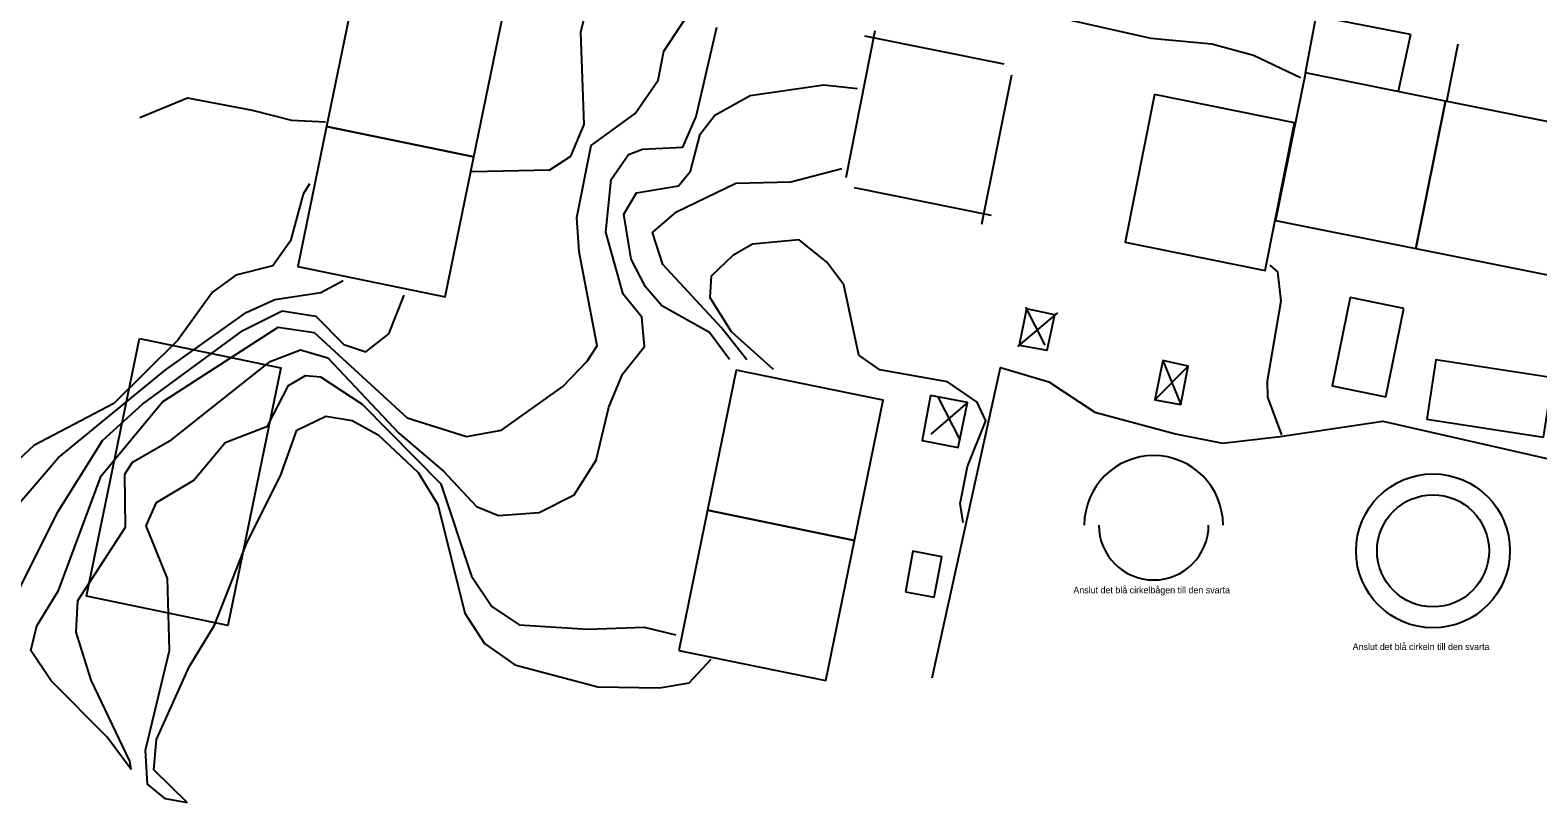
# Model space of a CAD drawing. Extents: x 1517610 to 1517815, y 6495294 to 6495395.
# Drawn here: x 1517678 to 1517766.9, y 6495294.4 to 6495340 of the extents above; entities that cross this region are included whole.
import ezdxf

# ---------------------------------------------------------------- set-up
doc = ezdxf.new("R2010")
doc.units = 0
for name, color, linetype in [('Baskarta', 7, 'Continuous'), ('Instruktioner', 7, 'Continuous'), ('Lager 1', 7, 'Continuous')]:
    doc.layers.add(name, color=color, linetype=linetype)

msp = doc.modelspace()

# ---------------------------------------------------------------- linework, layer by layer
at = {"layer": 'Baskarta'}
for points in [[(1517704.184, 6495332.51), (1517705.894, 6495340.815), (1517697.216, 6495342.603), (1517695.505, 6495334.298)], [(1517751.461, 6495328.762), (1517759.724, 6495327.112), (1517761.467, 6495335.803), (1517753.212, 6495337.462)], [(1517752.566, 6495334.522), (1517744.327, 6495336.181), (1517742.583, 6495327.489), (1517750.835, 6495325.823)], [(1517769.718, 6495334.144), (1517761.467, 6495335.803), (1517759.724, 6495327.112), (1517767.99, 6495325.461)], [(1517695.505, 6495334.298), (1517693.807, 6495326.054), (1517702.486, 6495324.271), (1517704.184, 6495332.51)], [(1517759.018, 6495323.577), (1517755.861, 6495324.224), (1517754.795, 6495319.019), (1517757.952, 6495318.372)], [(1517736.767, 6495323.56), (1517736.343, 6495321.414), (1517737.999, 6495321.122), (1517738.444, 6495323.195)], [(1517744.808, 6495320.519), (1517744.343, 6495318.191), (1517745.868, 6495317.908), (1517746.302, 6495320.186)], [(1517716.268, 6495303.421), (1517724.948, 6495301.662), (1517726.632, 6495309.911), (1517717.959, 6495311.685)], [(1517729.632, 6495306.886), (1517731.329, 6495306.562), (1517731.784, 6495308.941), (1517730.077, 6495309.274)]]:
    msp.add_lwpolyline(points, close=True, dxfattribs=at)
for points in [[(1517683.978, 6495296.401), (1517682.571, 6495298.314), (1517679.264, 6495301.623), (1517678.066, 6495303.419), (1517678.425, 6495304.88), (1517679.704, 6495306.959), (1517682.221, 6495313.712), (1517685.834, 6495318.082), (1517692.652, 6495322.478), (1517694.769, 6495322.16), (1517700.25, 6495317.141), (1517703.758, 6495316.027), (1517705.821, 6495316.412), (1517709.435, 6495318.97), (1517710.872, 6495320.471), (1517711.456, 6495321.385), (1517710.39, 6495326.907), (1517710.263, 6495328.946), (1517711.103, 6495333.189), (1517713.694, 6495335.066), (1517715.053, 6495337.028), (1517715.387, 6495338.739), (1517717.438, 6495341.843)], [(1517704.065, 6495331.652), (1517708.666, 6495331.742), (1517709.901, 6495332.555), (1517710.695, 6495334.416), (1517710.503, 6495339.86), (1517710.869, 6495341.385)], [(1517735.619, 6495341.413), (1517744.097, 6495339.514), (1517747.706, 6495339.166), (1517750.152, 6495338.511), (1517752.935, 6495337.193)], [(1517753.212, 6495337.462), (1517753.845, 6495340.805)], [(1517759.403, 6495339.726), (1517753.845, 6495340.805)], [(1517683.978, 6495296.401), (1517683.908, 6495296.901), (1517681.623, 6495301.68), (1517680.745, 6495304.507), (1517680.83, 6495306.374), (1517683.654, 6495310.698), (1517683.612, 6495313.807), (1517684.057, 6495314.518), (1517686.376, 6495315.848), (1517692.176, 6495320.455), (1517693.965, 6495321.135), (1517695.567, 6495320.661), (1517699.758, 6495316.234), (1517702.401, 6495313.995), (1517704.333, 6495311.902), (1517705.637, 6495311.38), (1517708.044, 6495311.561), (1517710.097, 6495312.595), (1517711.392, 6495314.642), (1517712.148, 6495317.753), (1517712.943, 6495319.699), (1517714.238, 6495321.333), (1517714.088, 6495323.074), (1517712.986, 6495324.426), (1517711.974, 6495328.065), (1517712.284, 6495331.182), (1517713.298, 6495332.652), (1517714.134, 6495332.973), (1517716.509, 6495333.084), (1517717.296, 6495334.897), (1517718.503, 6495340.148)], [(1517759.403, 6495339.726), (1517758.688, 6495336.361)], [(1517761.554, 6495335.785), (1517762.213, 6495339.181)], [(1517684.5, 6495334.83), (1517687.304, 6495335.997), (1517691.116, 6495335.266), (1517693.43, 6495334.666), (1517695.43, 6495334.583)], [(1517694.503, 6495330.925), (1517694.114, 6495330.316), (1517693.381, 6495327.557), (1517692.335, 6495326.095), (1517690.149, 6495325.538), (1517688.783, 6495324.53), (1517686.73, 6495321.7), (1517682.953, 6495317.986), (1517678.244, 6495315.497), (1517676.69, 6495314.043), (1517674.619, 6495306.322), (1517673.846, 6495305.315), (1517673.495, 6495305.11)], [(1517751.124, 6495326.13), (1517751.577, 6495325.731), (1517751.767, 6495324.012), (1517750.951, 6495319.286), (1517750.983, 6495318.348), (1517751.813, 6495316.122)], [(1517677.223, 6495302.637), (1517676.324, 6495303.574), (1517675.362, 6495305.3), (1517675.429, 6495308.316), (1517676.091, 6495310.62), (1517679.681, 6495314.772), (1517685.99, 6495319.942), (1517690.768, 6495323.336), (1517692.447, 6495324.111), (1517695.158, 6495324.511), (1517696.477, 6495325.232)], [(1517677.223, 6495302.637), (1517676.496, 6495303.84), (1517676.885, 6495306.051), (1517679.669, 6495311.608), (1517682.283, 6495315.798), (1517684.64, 6495317.941), (1517690.558, 6495322.282), (1517692.893, 6495323.432), (1517694.87, 6495323.121), (1517696.519, 6495321.451), (1517697.825, 6495321.022), (1517699.167, 6495322.078), (1517700.079, 6495324.352)], [(1517731.214, 6495301.803), (1517735.236, 6495320.103), (1517738.086, 6495319.25), (1517740.808, 6495317.471), (1517745.558, 6495316.191), (1517748.331, 6495315.638), (1517751.732, 6495316.033), (1517757.783, 6495316.926), (1517769.105, 6495314.362), (1517769.487, 6495319.714), (1517770.49, 6495322.814), (1517770.616, 6495322.713)], [(1517746.302, 6495320.186), (1517744.343, 6495318.191)], [(1517744.808, 6495320.519), (1517745.868, 6495317.908)], [(1517687.293, 6495294.443), (1517685.996, 6495294.684), (1517684.948, 6495295.542), (1517684.829, 6495297.55), (1517686.238, 6495303.426), (1517686.118, 6495307.66), (1517684.865, 6495310.769), (1517685.465, 6495312.144), (1517687.675, 6495313.458), (1517689.517, 6495315.687), (1517692.024, 6495316.634), (1517693.264, 6495319.034), (1517694.263, 6495319.621), (1517695.138, 6495319.55), (1517697.592, 6495317.936), (1517702.23, 6495313.237), (1517704.047, 6495307.808), (1517705.244, 6495306.02), (1517706.854, 6495304.927), (1517710.909, 6495304.674), (1517714.221, 6495304.794), (1517716.096, 6495304.334)], [(1517731.55, 6495318.36), (1517732.833, 6495315.841)], [(1517733.298, 6495318.038), (1517731.136, 6495316.175)], [(1517687.293, 6495294.443), (1517685.314, 6495296.394), (1517685.47, 6495298.175), (1517687.403, 6495302.466), (1517688.893, 6495304.92), (1517690.796, 6495309.766), (1517692.792, 6495313.713), (1517693.743, 6495316.409), (1517695.468, 6495317.223), (1517697.015, 6495316.974), (1517698.54, 6495316.131), (1517700.893, 6495313.915), (1517702.067, 6495312.033), (1517703.658, 6495305.629), (1517704.808, 6495303.825), (1517706.606, 6495302.568), (1517711.498, 6495301.283), (1517715.123, 6495301.216), (1517716.873, 6495301.515), (1517718.176, 6495302.906)]]:
    msp.add_lwpolyline(points, dxfattribs=at)
msp.add_circle((1517760.74, 6495309.29), 4.536, dxfattribs=at)
msp.add_arc((1517744.27, 6495310.816), 3.239, 180, 0, dxfattribs=at)
at = {"layer": 'Lager 1'}
for p, q in [((1517727.836, 6495339.936), (1517726.117, 6495331.267)), ((1517735.448, 6495337.968), (1517727.238, 6495339.621)), ((1517734.146, 6495328.544), (1517735.91, 6495337.337)), ((1517726.609, 6495330.714), (1517734.695, 6495329.081)), ((1517736.717, 6495323.659), (1517737.847, 6495321.423)), ((1517738.596, 6495323.324), (1517736.24, 6495321.327))]:
    msp.add_line(p, q, dxfattribs=at)
for points in [[(1517719.268, 6495320.568), (1517718.081, 6495322.156), (1517715.267, 6495323.724), (1517714.313, 6495324.856), (1517713.468, 6495326.48), (1517713.021, 6495329.137), (1517713.784, 6495330.387), (1517716.253, 6495330.81), (1517716.955, 6495331.671), (1517717.531, 6495333.851), (1517718.39, 6495334.977), (1517720.475, 6495336.135), (1517724.818, 6495336.747), (1517726.803, 6495336.538)], [(1517720.276, 6495320.549), (1517718.792, 6495322.443), (1517715.327, 6495326.178), (1517714.724, 6495328.059), (1517716.137, 6495329.279), (1517719.636, 6495330.954), (1517722.87, 6495331.043), (1517725.877, 6495331.818)], [(1517733.036, 6495310.966), (1517732.863, 6495312.09), (1517733.283, 6495314.271), (1517734.367, 6495316.951), (1517733.866, 6495318.06), (1517732.107, 6495319.262), (1517728.114, 6495319.953), (1517726.879, 6495320.827), (1517725.993, 6495324.968), (1517724.999, 6495326.303), (1517723.358, 6495327.621), (1517720.623, 6495327.369), (1517719.46, 6495326.704), (1517718.188, 6495325.477), (1517718.095, 6495324.219), (1517719.363, 6495322.228), (1517721.825, 6495320.003)]]:
    msp.add_lwpolyline(points, dxfattribs=at)
for points in [[(1517684.468, 6495321.798), (1517692.809, 6495320.084), (1517689.688, 6495304.899), (1517681.347, 6495306.613)], [(1517767.256, 6495315.984), (1517767.799, 6495319.489), (1517760.914, 6495320.554), (1517760.372, 6495317.05)], [(1517719.65, 6495319.945), (1517717.959, 6495311.685), (1517726.632, 6495309.911), (1517728.32, 6495318.174)], [(1517731.119, 6495318.442), (1517730.617, 6495315.806), (1517732.744, 6495315.391), (1517733.298, 6495318.038)]]:
    msp.add_lwpolyline(points, close=True, dxfattribs=at)
msp.add_circle((1517760.74, 6495309.29), 3.303, dxfattribs=at)
msp.add_arc((1517744.27, 6495310.816), 4.091, 0, 180, dxfattribs=at)

# ---------------------------------------------------------------- texts
at = {"layer": 'Instruktioner'}
for s, p in [('Anslut det blå cirkelbågen till den svarta', (1517739.535, 6495306.787)), ('Anslut det blå cirkeln till den svarta', (1517756.002, 6495303.448))]:
    msp.add_text(s, height=0.39176, dxfattribs=at).set_placement(p)

doc.saveas('drawing.dxf')
